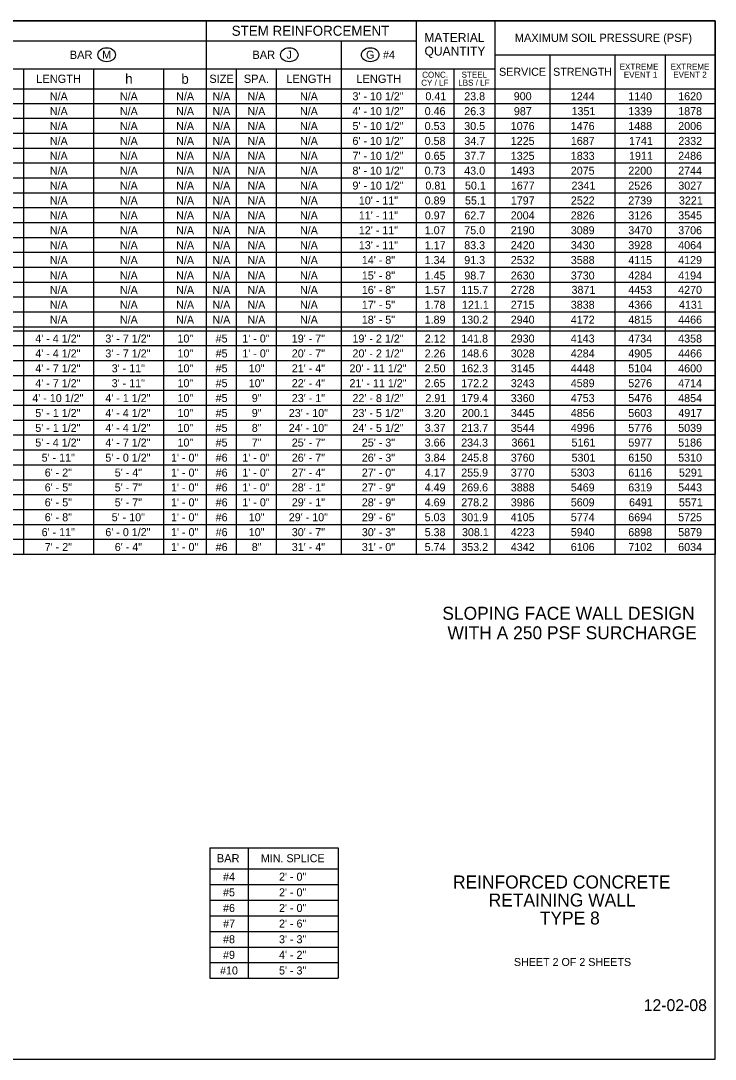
# Model space of a CAD drawing. Extents: x 99862 to 103151, y 100000 to 105076.
# Drawn here: x 101763 to 103151, y 103000 to 105076 of the extents above; entities that cross this region are included whole.
import ezdxf

# ---------------------------------------------------------------- set-up
doc = ezdxf.new("R2010")
doc.units = 0
for name, color, linetype in [('Level 1', 7, 'Continuous'), ('Level 20', 7, 'Continuous'), ('Level 21', 7, 'Continuous'), ('Level 4', 7, 'Continuous'), ('Level 60', 7, 'Continuous'), ('Level 62', 7, 'Continuous'), ('Level 63', 7, 'Continuous')]:
    doc.layers.add(name, color=color, linetype=linetype)

msp = doc.modelspace()

# ---------------------------------------------------------------- linework, layer by layer
at = {"layer": 'Level 1'}
msp.add_lwpolyline([(99862, 102999.5), (103151, 102999.5), (103151, 105075.5), (99862, 105075.5)], close=True, dxfattribs=at)
at = {"layer": 'Level 20'}
for centre in [(101934.5, 105007.5), (102299.5, 105007.5), (102461.4, 105007.5)]:
    msp.add_ellipse(centre, major_axis=(-17.5, 0), ratio=0.8, dxfattribs=at)
at = {"layer": 'Level 4'}
for p, q in [((102134, 104008.6), (102134, 105075.5)), ((102554, 104008.6), (102554, 105075.5)), ((102711, 104008.6), (102711, 105075.5)), ((100404, 105035.5), (102554, 105035.5)), ((102404, 104008.6), (102404, 105035.5)), ((102711, 105007.5), (103151, 105007.5)), ((102821, 104008.6), (102821, 105007.5)), ((102951, 104008.6), (102951, 105007.5)), ((100004, 104979.5), (102711, 104979.5)), ((101769, 104008.6), (101769, 104979.5)), ((101909, 104008.6), (101909, 104979.5)), ((102049, 104008.6), (102049, 104979.5)), ((102194, 104008.6), (102194, 104979.5)), ((102274, 104008.6), (102274, 104979.5)), ((102629, 104008.6), (102629, 104979.5)), ((99929, 104939.5), (103151, 104939.5)), ((103151, 104909.7), (99929, 104909.7)), ((103151, 104880), (99929, 104880)), ((103151, 104850.2), (99929, 104850.2)), ((103151, 104820.4), (99929, 104820.4)), ((103151, 104790.6), (99929, 104790.6)), ((103151, 104760.9), (99929, 104760.9)), ((103151, 104731.1), (99929, 104731.1)), ((103151, 104701.3), (99929, 104701.3)), ((103151, 104671.6), (99929, 104671.6)), ((103151, 104641.8), (99929, 104641.8)), ((103151, 104612), (99929, 104612)), ((103151, 104582.2), (99929, 104582.2)), ((103151, 104552.5), (99929, 104552.5)), ((103151, 104522.7), (99929, 104522.7)), ((103151, 104492.9), (99929, 104492.9)), ((103151, 104463.2), (99929, 104463.2)), ((103151, 104455.2), (99929, 104455.2)), ((103151, 104425.4), (99929, 104425.4)), ((103151, 104395.6), (99929, 104395.6)), ((103151, 104365.8), (99929, 104365.8)), ((103151, 104336.1), (99929, 104336.1)), ((103151, 104306.3), (99929, 104306.3)), ((103151, 104276.5), (99929, 104276.5)), ((103151, 104246.8), (99929, 104246.8)), ((103151, 104217), (99929, 104217)), ((103151, 104187.2), (99929, 104187.2)), ((103151, 104157.4), (99929, 104157.4)), ((103151, 104127.7), (99929, 104127.7)), ((103151, 104097.9), (99929, 104097.9)), ((103151, 104068.1), (99929, 104068.1)), ((103151, 104038.4), (99929, 104038.4)), ((102140.6, 103422.4), (102397.6, 103422.4)), ((102140.6, 103422.4), (102140.6, 103161.3)), ((102217.2, 103422.4), (102217.2, 103161.3)), ((102397.6, 103422.4), (102397.6, 103161.3)), ((102140.6, 103380.1), (102397.6, 103380.1)), ((102140.6, 103348.8), (102397.6, 103348.8)), ((102140.6, 103317.6), (102397.6, 103317.6)), ((102140.6, 103286.3), (102397.6, 103286.3)), ((102140.6, 103255.1), (102397.6, 103255.1)), ((102140.6, 103223.8), (102397.6, 103223.8)), ((102140.6, 103192.6), (102397.6, 103192.6)), ((102140.6, 103161.3), (102397.6, 103161.3))]:
    msp.add_line(p, q, dxfattribs=at)
for points in [[(99929, 105075.5), (103151, 105075.5)], [(103151, 104008.6), (99929, 104008.6), (99929, 105075.5)], [(103151, 105075.5), (103151, 104008.6)], [(103051, 105007.5), (103051, 104012.6)]]:
    msp.add_lwpolyline(points, dxfattribs=at)
at = {"layer": 'Level 60'}
msp.add_line((103151, 105075.5), (103151, 105075.5), dxfattribs=at)

# ---------------------------------------------------------------- texts
at = {"layer": 'Level 1'}
msp.add_text('12-02-08', height=23.62, dxfattribs=at).set_placement((103008, 103095.8))
at = {"layer": 'Level 20'}
for s, height, p in [('STEM REINFORCEMENT', 20, (102184.4, 105045.5)), ('MATERIAL', 18, (102569.5, 105033)), ('MAXIMUM SOIL PRESSURE (PSF)', 16.5, (102750.3, 105033.3)), ('BAR', 16.5, (101860.8, 104999.3)), ('M', 16, (101925.5, 104999.7)), ('BAR', 16.5, (102225.8, 104999.3)), ('J', 16, (102294.2, 104999.8)), ('G', 16, (102453, 104999.6)), ('#4', 16, (102486.9, 104999.5)), ('QUANTITY', 18, (102569.9, 105006)), ('EXTREME ', 12, (102960, 104977.5)), ('EXTREME', 12, (103061.8, 104977.8)), ('LENGTH', 16.5, (101793.7, 104951.3)), ('h', 20, (101971.6, 104949.5)), ('b', 20, (102083.8, 104949.5)), ('SIZE', 16.5, (102139.7, 104951.3)), ('SPA.', 16.5, (102208.6, 104951.3)), ('LENGTH', 16.5, (102293.7, 104951.3)), ('LENGTH', 16.5, (102433.7, 104951.3)), ('CONC.', 12, (102565.2, 104961.6)), ('STEEL', 12, (102644, 104961.8)), ('SERVICE', 16, (102718.9, 104965.5)), ('STRENGTH', 16, (102827, 104965.5)), ('EVENT 1', 12, (102968.3, 104961.5)), ('EVENT 2', 12, (103067.1, 104961.8)), ('CY / LF', 12, (102563.3, 104945.6)), ('LBS / LF', 12, (102637.4, 104945.8))]:
    msp.add_text(s, height=height, dxfattribs=at).set_placement(p)
for p in [(101821, 104916.6), (101961, 104916.6), (102073.5, 104916.6), (102146, 104916.6), (102216, 104916.6), (102321, 104916.6), (101821, 104886.8), (101961, 104886.8), (102073.5, 104886.8), (102146, 104886.8), (102216, 104886.8), (102321, 104886.8), (101821, 104857.1), (101961, 104857.1), (102073.5, 104857.1), (102146, 104857.1), (102216, 104857.1), (102321, 104857.1), (101821, 104827.3), (101961, 104827.3), (102073.5, 104827.3), (102146, 104827.3), (102216, 104827.3), (102321, 104827.3), (101821, 104797.5), (101961, 104797.5), (102073.5, 104797.5), (102146, 104797.5), (102216, 104797.5), (102321, 104797.5), (101821, 104767.8), (101961, 104767.8), (102073.5, 104767.8), (102146, 104767.8), (102216, 104767.8), (102321, 104767.8), (101821, 104738), (101961, 104738), (102073.5, 104738), (102146, 104738), (102216, 104738), (102321, 104738), (101821, 104708.2), (101961, 104708.2), (102073.5, 104708.2), (102146, 104708.2), (102216, 104708.2), (102321, 104708.2), (101821, 104678.4), (101961, 104678.4), (102073.5, 104678.4), (102146, 104678.4), (102216, 104678.4), (102321, 104678.4), (101821, 104648.7), (101961, 104648.7), (102073.5, 104648.7), (102146, 104648.7), (102216, 104648.7), (102321, 104648.7), (101821, 104618.9), (101961, 104618.9), (102073.5, 104618.9), (102146, 104618.9), (102216, 104618.9), (102321, 104618.9), (101821, 104589.1), (101961, 104589.1), (102073.5, 104589.1), (102146, 104589.1), (102216, 104589.1), (102321, 104589.1), (101821, 104558.3), (101961, 104558.3), (102073.5, 104558.3), (102146, 104558.3), (102216, 104558.3), (102321, 104558.3), (101821, 104529.6), (101961, 104529.6), (102073.5, 104529.6), (102146, 104529.6), (102216, 104529.6), (102321, 104529.6), (101821, 104499.8), (101961, 104499.8), (102073.5, 104499.8), (102146, 104499.8), (102216, 104499.8), (102321, 104499.8), (101821, 104470), (101961, 104470), (102073.5, 104470), (102146, 104470), (102216, 104470), (102321, 104470), (102321, 104470)]:
    msp.add_text('N/A', height=16, rotation=360, dxfattribs=at).set_placement(p)
at = {"layer": 'Level 21'}
for s, p in [('SLOPING FACE WALL DESIGN ', (102605.5, 103878)), ('WITH A 250 PSF SURCHARGE', (102615.7, 103839))]:
    msp.add_text(s, height=26, rotation=360, dxfattribs=at).set_placement(p)
at = {"layer": 'Level 4'}
for s, height, p in [('3\' - 10 1/2"', 16, (102425.9, 104916.6)), ('0.41', 16, (102571.7, 104916.6)), ('23.8', 16, (102649.3, 104916.6)), ('900', 16, (102748.3, 104916.6)), ('1244', 16, (102862.3, 104916.6)), ('1140', 16, (102977.2, 104916.6)), ('1620', 16, (103077, 104916.6)), ('4\' - 10 1/2"', 16, (102425.9, 104886.8)), ('0.46', 16, (102570.2, 104886.8)), ('26.3', 16, (102649.3, 104886.8)), ('987', 16, (102748.5, 104886.8)), ('1351', 16, (102863.8, 104886.8)), ('1339', 16, (102977.2, 104886.8)), ('1878', 16, (103077, 104886.8)), ('5\' - 10 1/2"', 16, (102425.9, 104857.1)), ('0.53', 16, (102570.2, 104857.1)), ('30.5', 16, (102649.3, 104857.1)), ('1076', 16, (102742.3, 104857.1)), ('1476', 16, (102862.3, 104857.1)), ('1488', 16, (102977.2, 104857.1)), ('2006', 16, (103077, 104857.1)), ('6\' - 10 1/2"', 16, (102425.9, 104827.3)), ('0.58', 16, (102570.2, 104827.3)), ('34.7', 16, (102649.5, 104827.3)), ('1225', 16, (102742.3, 104827.3)), ('1687', 16, (102862.4, 104827.3)), ('1741', 16, (102978.7, 104827.3)), ('2332', 16, (103077.2, 104827.3)), ('7\' - 10 1/2"', 16, (102425.9, 104797.5)), ('0.65', 16, (102570.2, 104797.5)), ('37.7', 16, (102649.5, 104797.5)), ('1325', 16, (102742.3, 104797.5)), ('1833', 16, (102862.3, 104797.5)), ('1911', 16, (102978.7, 104797.5)), ('2486', 16, (103077, 104797.5)), ('8\' - 10 1/2"', 16, (102425.9, 104767.8)), ('0.73', 16, (102570.2, 104767.8)), ('43.0', 16, (102649.3, 104767.8)), ('1493', 16, (102742.3, 104767.8)), ('2075', 16, (102862.3, 104767.8)), ('2200', 16, (102977.2, 104767.8)), ('2744', 16, (103077, 104767.8)), ('9\' - 10 1/2"', 16, (102425.9, 104738)), ('0.81', 16, (102571.7, 104738)), ('50.1', 16, (102650.8, 104738)), ('1677', 16, (102742.4, 104738)), ('2341', 16, (102863.8, 104738)), ('2526', 16, (102977.2, 104738)), ('3027', 16, (103077.2, 104738)), ('10\' - 11"', 16, (102438.6, 104708.2)), ('0.89', 16, (102570.2, 104708.2)), ('55.1', 16, (102650.8, 104708.2)), ('1797', 16, (102742.4, 104708.2)), ('2522', 16, (102862.4, 104708.2)), ('2739', 16, (102977.2, 104708.2)), ('3221', 16, (103078.5, 104708.2)), ('11\' - 11"', 16, (102438.6, 104678.4)), ('0.97', 16, (102570.4, 104678.4)), ('62.7', 16, (102649.5, 104678.4)), ('2004', 16, (102742.3, 104678.4)), ('2826', 16, (102862.3, 104678.4)), ('3126', 16, (102977.2, 104678.4)), ('3545', 16, (103077, 104678.4)), ('12\' - 11"', 16, (102438.6, 104648.7)), ('1.07', 16, (102570.4, 104648.7)), ('75.0', 16, (102649.3, 104648.7)), ('2190', 16, (102742.3, 104648.7)), ('3089', 16, (102862.3, 104648.7)), ('3470', 16, (102977.2, 104648.7)), ('3706', 16, (103077, 104648.7)), ('13\' - 11"', 16, (102438.6, 104618.9)), ('1.17', 16, (102570.4, 104618.9)), ('83.3', 16, (102649.3, 104618.9)), ('2420', 16, (102742.3, 104618.9)), ('3430', 16, (102862.3, 104618.9)), ('3928', 16, (102977.2, 104618.9)), ('4064', 16, (103077, 104618.9)), ('14\' - 8"', 16, (102444.6, 104589.1)), ('1.34', 16, (102570.2, 104589.1)), ('91.3', 16, (102649.3, 104589.1)), ('2532', 16, (102742.4, 104589.1)), ('3588', 16, (102862.3, 104589.1)), ('4115', 16, (102977.2, 104589.1)), ('4129', 16, (103077, 104589.1)), ('15\' - 8"', 16, (102444.6, 104558.3)), ('1.45', 16, (102570.2, 104558.3)), ('98.7', 16, (102649.5, 104558.3)), ('2630', 16, (102742.3, 104558.3)), ('3730', 16, (102862.3, 104558.3)), ('4284', 16, (102977.2, 104558.3)), ('4194', 16, (103077, 104558.3)), ('16\' - 8"', 16, (102444.6, 104529.6)), ('1.57', 16, (102570.4, 104529.6)), ('115.7', 16, (102643.4, 104529.6)), ('2728', 16, (102742.3, 104529.6)), ('3871', 16, (102863.8, 104529.6)), ('4453', 16, (102977.2, 104529.6)), ('4270', 16, (103077, 104529.6)), ('17\' - 5"', 16, (102444.6, 104499.8)), ('1.78', 16, (102570.2, 104499.8)), ('121.1', 16, (102644.8, 104499.8)), ('2715', 16, (102742.3, 104499.8)), ('3838', 16, (102862.3, 104499.8)), ('4366', 16, (102977.2, 104499.8)), ('4131', 16, (103078.5, 104499.8)), ('18\' - 5"', 16, (102444.6, 104470)), ('1.89', 16, (102570.2, 104470)), ('130.2', 16, (102643.4, 104470)), ('2940', 16, (102742.3, 104470)), ('4172', 16, (102862.4, 104470)), ('4815', 16, (102977.2, 104470)), ('4466', 16, (103077, 104470)), ('4\' - 4 1/2"', 16, (101791.9, 104432.3)), ('3\' - 7 1/2"', 16, (101931.9, 104432.3)), ('19\' - 7"', 16, (102304.6, 104432.3)), ('19\' - 2 1/2"', 16, (102425.9, 104432.3)), ('2.12', 16, (102570.4, 104432.3)), ('141.8', 16, (102643.3, 104432.3)), ('2930', 16, (102742.3, 104432.3)), ('4143', 16, (102862.3, 104432.3)), ('4734', 16, (102977.2, 104432.3)), ('4358', 16, (103077, 104432.3)), ('4\' - 4 1/2"', 16, (101791.9, 104402.5)), ('3\' - 7 1/2"', 16, (101931.9, 104402.5)), ('20\' - 7"', 16, (102304.6, 104402.5)), ('20\' - 2 1/2"', 16, (102425.9, 104402.5)), ('2.26', 16, (102570.2, 104402.5)), ('148.6', 16, (102643.3, 104402.5)), ('3028', 16, (102742.3, 104402.5)), ('4284', 16, (102862.3, 104402.5)), ('4905', 16, (102977.2, 104402.5)), ('4466', 16, (103077, 104402.5)), ('4\' - 7 1/2"', 16, (101791.9, 104372.7)), ('3\' - 11"', 16, (101944.6, 104372.7)), ('21\' - 4"', 16, (102304.6, 104372.7)), ('20\' - 11 1/2"', 16, (102419.9, 104372.7)), ('2.50', 16, (102570.2, 104372.7)), ('162.3', 16, (102643.3, 104372.7)), ('3145', 16, (102742.3, 104372.7)), ('4448', 16, (102862.3, 104372.7)), ('5104', 16, (102977.2, 104372.7)), ('4600', 16, (103077, 104372.7)), ('4\' - 7 1/2"', 16, (101791.9, 104343)), ('3\' - 11"', 16, (101944.6, 104343)), ('22\' - 4"', 16, (102304.6, 104343)), ('21\' - 11 1/2"', 16, (102419.9, 104343)), ('2.65', 16, (102570.2, 104343)), ('172.2', 16, (102643.4, 104343)), ('3243', 16, (102742.3, 104343)), ('4589', 16, (102862.3, 104343)), ('5276', 16, (102977.2, 104343)), ('4714', 16, (103077, 104343)), ('4\' - 10 1/2"', 16, (101785.9, 104313.2)), ('4\' - 1 1/2"', 16, (101931.9, 104313.2)), ('23\' - 1"', 16, (102304.6, 104313.2)), ('22\' - 8 1/2"', 16, (102425.9, 104313.2)), ('2.91', 16, (102571.7, 104313.2)), ('179.4', 16, (102643.3, 104313.2)), ('3360', 16, (102742.3, 104313.2)), ('4753', 16, (102862.3, 104313.2)), ('5476', 16, (102977.2, 104313.2)), ('4854', 16, (103077, 104313.2)), ('5\' - 1 1/2"', 16, (101791.9, 104283.4)), ('4\' - 4 1/2"', 16, (101931.9, 104283.4)), ('23\' - 10"', 16, (102298.6, 104283.4)), ('23\' - 5 1/2"', 16, (102425.9, 104283.4)), ('3.20', 16, (102570.2, 104283.4)), ('200.1', 16, (102644.8, 104283.4)), ('3445', 16, (102742.3, 104283.4)), ('4856', 16, (102862.3, 104283.4)), ('5603', 16, (102977.2, 104283.4)), ('4917', 16, (103077.2, 104283.4)), ('5\' - 1 1/2"', 16, (101791.9, 104253.6)), ('4\' - 4 1/2"', 16, (101931.9, 104253.6)), ('24\' - 10"', 16, (102298.6, 104253.6)), ('24\' - 5 1/2"', 16, (102425.9, 104253.6)), ('3.37', 16, (102570.4, 104253.6)), ('213.7', 16, (102643.4, 104253.6)), ('3544', 16, (102742.3, 104253.6)), ('4996', 16, (102862.3, 104253.6)), ('5776', 16, (102977.2, 104253.6)), ('5039', 16, (103077, 104253.6)), ('5\' - 4 1/2"', 16, (101791.9, 104224.3)), ('4\' - 7 1/2"', 16, (101931.9, 104224.3)), ('25\' - 7"', 16, (102304.6, 104224.3)), ('25\' - 3"', 16, (102444.6, 104224.3)), ('3.66', 16, (102570.2, 104224.3)), ('234.3', 16, (102643.3, 104224.3)), ('3661', 16, (102743.8, 104224.3)), ('5161', 16, (102863.8, 104224.3)), ('5977', 16, (102977.4, 104224.3)), ('5186', 16, (103077, 104224.3)), ('5\' - 11"', 16, (101804.6, 104194.1)), ('5\' - 0 1/2"', 16, (101931.9, 104194.1)), ('26\' - 7"', 16, (102304.6, 104194.1)), ('26\' - 3"', 16, (102444.6, 104194.1)), ('3.84', 16, (102570.2, 104194.1)), ('245.8', 16, (102643.3, 104194.1)), ('3760', 16, (102742.3, 104194.1)), ('5301', 16, (102863.8, 104194.1)), ('6150', 16, (102977.2, 104194.1)), ('5310', 16, (103077, 104194.1)), ('6\' - 2"', 16, (101810.7, 104164.3)), ('5\' - 4"', 16, (101950.7, 104164.3)), ('27\' - 4"', 16, (102304.6, 104164.3)), ('27\' - 0"', 16, (102444.6, 104164.3)), ('4.17', 16, (102570.4, 104164.3)), ('255.9', 16, (102643.3, 104164.3)), ('3770', 16, (102742.3, 104164.3)), ('5303', 16, (102862.3, 104164.3)), ('6116', 16, (102977.2, 104164.3)), ('5291', 16, (103078.5, 104164.3)), ('6\' - 5"', 16, (101810.7, 104134.6)), ('5\' - 7"', 16, (101950.7, 104134.6)), ('28\' - 1"', 16, (102304.6, 104134.6)), ('27\' - 9"', 16, (102444.6, 104134.6)), ('4.49', 16, (102570.2, 104134.6)), ('269.6', 16, (102643.3, 104134.6)), ('3888', 16, (102742.3, 104134.6)), ('5469', 16, (102862.3, 104134.6)), ('6319', 16, (102977.2, 104134.6)), ('5443', 16, (103077, 104134.6)), ('6\' - 5"', 16, (101810.7, 104104.8)), ('5\' - 7"', 16, (101950.7, 104104.8)), ('29\' - 1"', 16, (102304.6, 104104.8)), ('28\' - 9"', 16, (102444.6, 104104.8)), ('4.69', 16, (102570.2, 104104.8)), ('278.2', 16, (102643.4, 104104.8)), ('3986', 16, (102742.3, 104104.8)), ('5609', 16, (102862.3, 104104.8)), ('6491', 16, (102978.7, 104104.8)), ('5571', 16, (103078.5, 104104.8)), ('6\' - 8"', 16, (101810.7, 104075)), ('5\' - 10"', 16, (101944.6, 104075)), ('29\' - 10"', 16, (102298.6, 104075)), ('29\' - 6"', 16, (102444.6, 104075)), ('5.03', 16, (102570.2, 104075)), ('301.9', 16, (102643.3, 104075)), ('4105', 16, (102742.3, 104075)), ('5774', 16, (102862.3, 104075)), ('6694', 16, (102977.2, 104075)), ('5725', 16, (103077, 104075)), ('6\' - 11"', 16, (101804.6, 104045.2)), ('6\' - 0 1/2"', 16, (101931.9, 104045.2)), ('30\' - 7"', 16, (102304.6, 104045.2)), ('30\' - 3"', 16, (102444.6, 104045.2)), ('5.38', 16, (102570.2, 104045.2)), ('308.1', 16, (102644.8, 104045.2)), ('4223', 16, (102742.3, 104045.2)), ('5940', 16, (102862.3, 104045.2)), ('6898', 16, (102977.2, 104045.2)), ('5879', 16, (103077, 104045.2)), ('7\' - 2"', 16, (101810.7, 104015.5)), ('6\' - 4"', 16, (101950.7, 104015.5)), ('31\' - 4"', 16, (102304.6, 104015.5)), ('31\' - 0"', 16, (102444.6, 104015.5)), ('5.74', 16, (102570.2, 104015.5)), ('353.2', 16, (102643.4, 104015.5)), ('4342', 16, (102742.4, 104015.5)), ('6106', 16, (102862.3, 104015.5)), ('7102', 16, (102977.4, 104015.5)), ('6034', 16, (103077, 104015.5)), ('BAR', 16.5, (102154.8, 103393)), ('MIN. SPLICE', 16, (102242.8, 103393.3)), ('#4', 16, (102167.2, 103356.4)), ('2\' - 0"', 16, (102279.1, 103356.4)), ('#5', 16, (102167.2, 103325.2)), ('2\' - 0"', 16, (102279.1, 103325.2)), ('#6', 16, (102167.2, 103293.9)), ('2\' - 0"', 16, (102279.1, 103293.9)), ('#7', 16, (102167.4, 103262.7)), ('2\' - 6"', 16, (102279.1, 103262.7)), ('#8', 16, (102167.2, 103231.4)), ('3\' - 3"', 16, (102279.1, 103231.4)), ('#9', 16, (102167.2, 103200.2)), ('4\' - 2"', 16, (102279.1, 103200.2)), ('#10', 16, (102161.2, 103168.9)), ('5\' - 3"', 16, (102279.1, 103168.9))]:
    msp.add_text(s, height=height, dxfattribs=at).set_placement(p)
for s, p in [('10"', (102076.1, 104432.3)), ('#5', (102152.4, 104432.3)), ('1\' - 0"', (102205.7, 104432.3)), ('10"', (102076.1, 104402.5)), ('#5', (102152.4, 104402.5)), ('1\' - 0"', (102205.7, 104402.5)), ('10"', (102076.1, 104372.7)), ('#5', (102152.4, 104372.7)), ('10"', (102218.6, 104372.7)), ('10"', (102076.1, 104343)), ('#5', (102152.4, 104343)), ('10"', (102218.6, 104343)), ('10"', (102076.1, 104313.2)), ('#5', (102152.4, 104313.2)), ('9"', (102224.6, 104313.2)), ('10"', (102076.1, 104283.4)), ('#5', (102152.4, 104283.4)), ('9"', (102224.6, 104283.4)), ('10"', (102076.1, 104253.6)), ('#5', (102152.4, 104253.6)), ('8"', (102224.6, 104253.6)), ('10"', (102076.1, 104224.3)), ('#5', (102152.4, 104224.3)), ('7"', (102224.6, 104224.3)), ('1\' - 0"', (102063.2, 104194.1)), ('#6', (102152.4, 104194.1)), ('1\' - 0"', (102205.7, 104194.1)), ('1\' - 0"', (102063.2, 104164.3)), ('#6', (102152.4, 104164.3)), ('1\' - 0"', (102205.7, 104164.3)), ('1\' - 0"', (102063.2, 104134.6)), ('#6', (102152.4, 104134.6)), ('1\' - 0"', (102205.7, 104134.6)), ('1\' - 0"', (102063.2, 104104.8)), ('#6', (102152.4, 104104.8)), ('1\' - 0"', (102205.7, 104104.8)), ('1\' - 0"', (102063.2, 104075)), ('#6', (102152.4, 104075)), ('10"', (102218.6, 104075)), ('1\' - 0"', (102063.2, 104045.2)), ('#6', (102152.4, 104045.2)), ('10"', (102218.6, 104045.2)), ('1\' - 0"', (102063.2, 104015.5)), ('#6', (102152.4, 104015.5)), ('8"', (102224.6, 104015.5))]:
    msp.add_text(s, height=16, rotation=360, dxfattribs=at).set_placement(p)
at = {"layer": 'Level 62'}
msp.add_text('SHEET 2 OF 2 SHEETS', height=16, dxfattribs=at).set_placement((102748.6, 103185.9))
at = {"layer": 'Level 63'}
for s, p in [('REINFORCED CONCRETE', (102626.8, 103340.8)), ('RETAINING WALL', (102698.1, 103304.8)), ('TYPE 8', (102800.4, 103268.8))]:
    msp.add_text(s, height=26, dxfattribs=at).set_placement(p)

doc.saveas('drawing.dxf')
